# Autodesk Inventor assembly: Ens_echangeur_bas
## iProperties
Shininess: 64.0
Length Units: 11269
Angle Units: 11279
Time Units: 11290
Mass Units: 11283
Length Display Precision: 3
Angle Display Precision: 2
Compacted: True
Created: 2008-04
Part Number: Ens_echangeur_bas
Document SubType Name: Assembly
Designer: plup
Density: 0.0
Volumn: 0.0
Area: 0.0
PropertySet Name: Model Information
Control State: 0
Master: False
Checked Out: False
Author: plup
